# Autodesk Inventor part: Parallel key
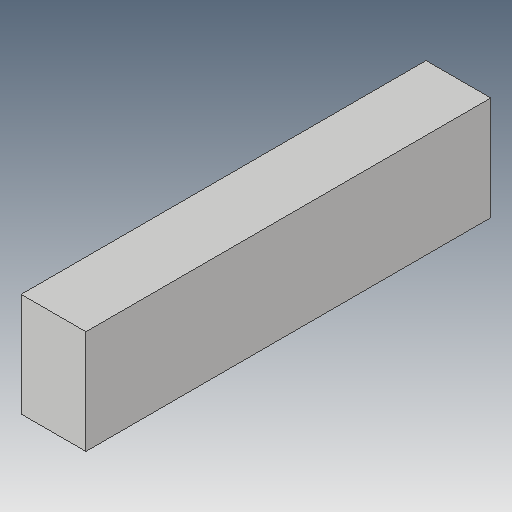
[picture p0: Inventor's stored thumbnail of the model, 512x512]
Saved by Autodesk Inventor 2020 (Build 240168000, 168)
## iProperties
Created: 2016-05
Part Number: Parallel key
Material: Generic
Document SubType Name: Modeling
Designer: CADCIM
Density: 1 g/cm^3
Appearance: Default
Author: CADCIM
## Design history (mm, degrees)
sketch "Sketch1"
  geometry: L1 (0, 0)-(16, 0); L2 (16, 0)-(16, -62.5); L3 (16, -62.5)-(0, -62.5); L4 (0, -62.5)-(0, 0)
  constraints: 8 end point, 2 parallel, 1 horizontal, 1 perpendicular
  dimensions: "d0" = 62.5 distance of L3.end L1.start; "d1" = 16 distance of L2.end L3.end
extrude "Extrusion1" new body sketch "Sketch1" distance "d2" = 10; taper "d3" = 0 deg
body "Solid1"
